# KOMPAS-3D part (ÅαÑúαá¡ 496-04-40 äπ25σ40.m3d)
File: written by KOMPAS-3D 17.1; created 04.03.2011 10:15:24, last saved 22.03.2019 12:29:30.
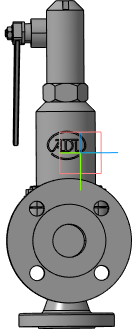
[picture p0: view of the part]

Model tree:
1. Плоскость XY
2. Плоскость ZX
3. Плоскость ZY
4. Ось X
5. Ось Y
6. Ось Z
7. Начало координат
8. Операция без истории:2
